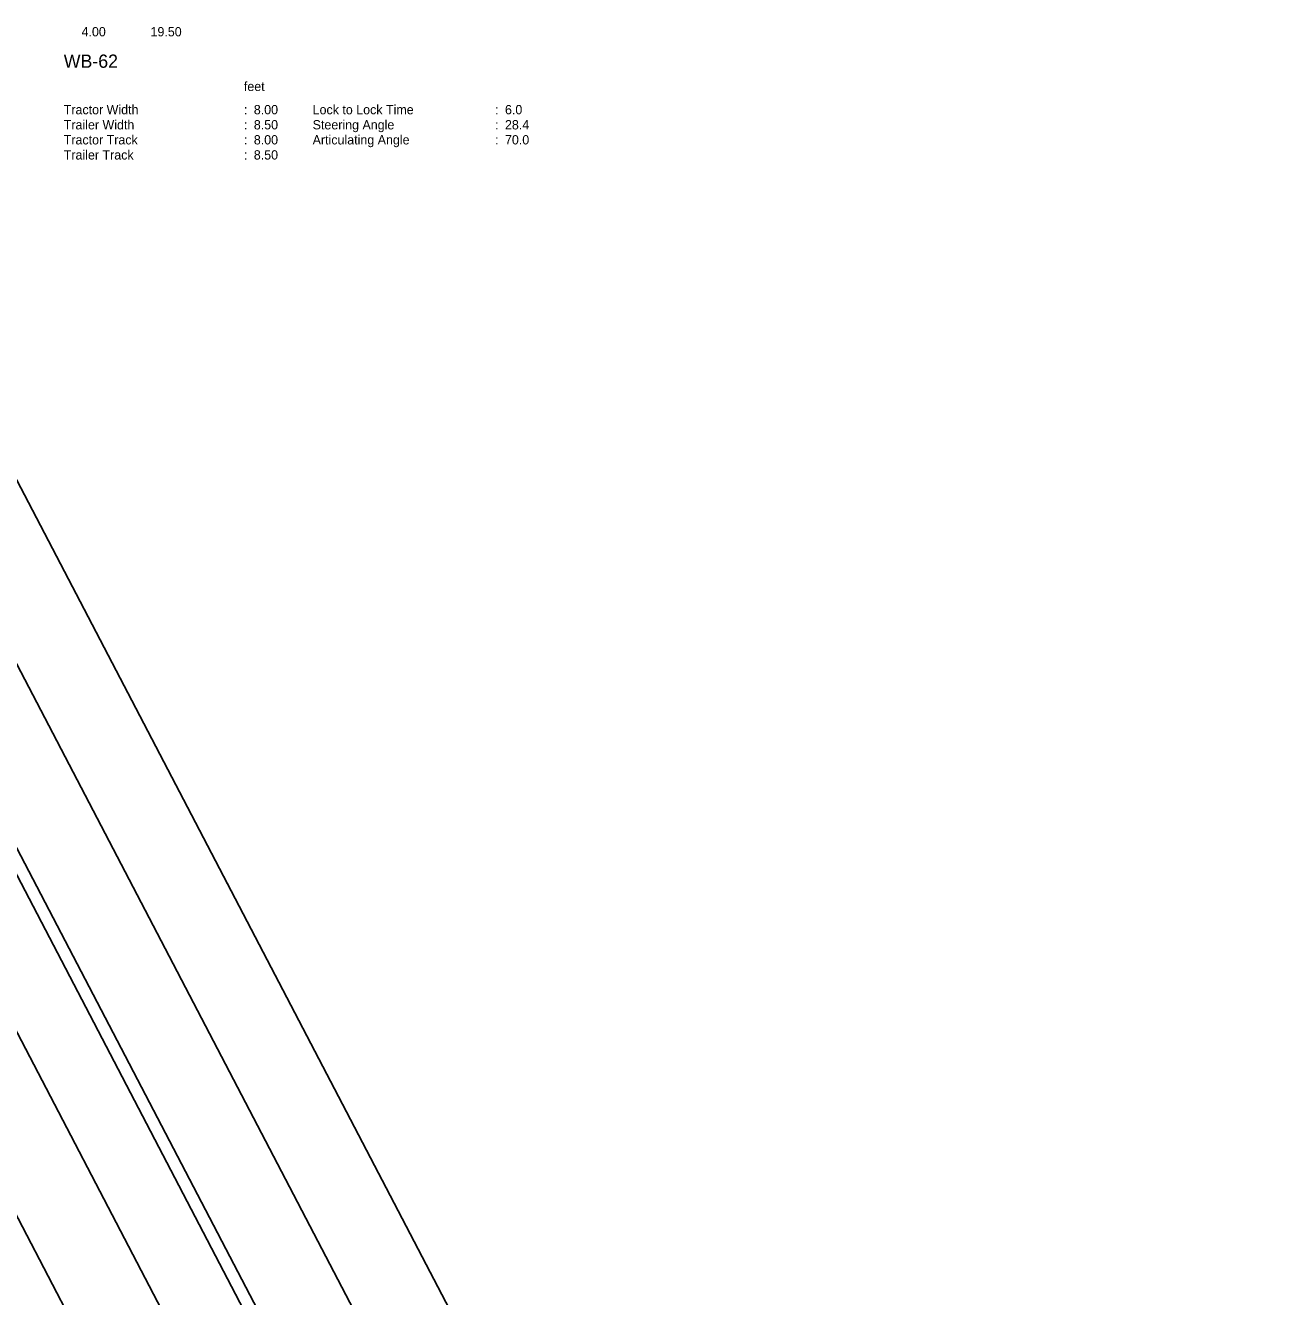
# Model space of a CAD drawing. Extents: x 2297881 to 2300600, y 559917 to 564426.
# Drawn here: x 2299069.8 to 2299244.6, y 562416.5 to 562595.7 of the extents above; entities that cross this region are included whole.
import ezdxf

# ---------------------------------------------------------------- set-up
doc = ezdxf.new("R2010")
doc.units = 0
for name, color, linetype in [('DR_X_Elev_Flow', 7, 'Continuous'), ('GE_X_Alignment', 7, 'Continuous'), ('PM_P_Lane_Line', 7, 'Continuous'), ('SV_X_Control_Cells_Found', 7, 'Continuous'), ('UT_X_Telecom_Cells', 7, 'Continuous'), ('VG_X_Cells', 7, 'Continuous')]:
    doc.layers.add(name, color=color, linetype=linetype)

msp = doc.modelspace()

# ---------------------------------------------------------------- linework, layer by layer
at = {"layer": 'GE_X_Alignment'}
msp.add_line((2298386.28, 563783.36), (2299396.64, 561847.4), dxfattribs=at)
at = {"layer": 'PM_P_Lane_Line'}
for p, q in [((2298467.65, 563579.35), (2299376.95, 561837.04)), ((2298843.32, 562963.26), (2299419.43, 561859.39))]:
    msp.add_line(p, q, dxfattribs=at)
at = {"layer": 'SV_X_Control_Cells_Found'}
msp.add_line((2299001.11, 562583.13), (2299365.23, 561885.43), dxfattribs=at)
at = {"layer": 'UT_X_Telecom_Cells'}
msp.add_line((2299022.38, 562594.23), (2299226.89, 562202.39), dxfattribs=at)
at = {"layer": 'VG_X_Cells'}
msp.add_line((2299011.74, 562588.68), (2299216.25, 562196.84), dxfattribs=at)

# ---------------------------------------------------------------- texts
at = {"layer": 'DR_X_Elev_Flow'}
for s, height, p in [('4.00', 1.312, (2299077.75, 562594.19)), ('19.50', 1.312, (2299087.47, 562594.19)), ('WB-62', 1.87, (2299075.24, 562589.76)), ('feet', 1.312, (2299100.63, 562586.48)), ('Tractor Width', 1.3123, (2299075.24, 562583.2)), ('8.00', 1.312, (2299102.03, 562583.2)), ('Lock to Lock Time', 1.3123, (2299110.32, 562583.2)), ('6.0', 1.312, (2299137.43, 562583.2)), (':', 1.31, (2299100.63, 562583.2)), (':', 1.31, (2299136.04, 562583.2)), ('Trailer Width', 1.3123, (2299075.24, 562581.07)), (':', 1.31, (2299100.63, 562581.07)), ('8.50', 1.312, (2299102.03, 562581.07)), ('Steering Angle', 1.3123, (2299110.32, 562581.07)), (':', 1.31, (2299136.04, 562581.07)), ('28.4', 1.312, (2299137.43, 562581.07)), ('Tractor Track', 1.3123, (2299075.24, 562578.95)), (':', 1.31, (2299100.63, 562578.95)), ('8.00', 1.312, (2299102.03, 562578.95)), ('Articulating Angle', 1.3123, (2299110.32, 562578.95)), (':', 1.31, (2299136.04, 562578.95)), ('70.0', 1.312, (2299137.43, 562578.95)), ('Trailer Track', 1.3123, (2299075.24, 562576.82)), (':', 1.31, (2299100.63, 562576.82)), ('8.50', 1.312, (2299102.03, 562576.82))]:
    msp.add_text(s, height=height, dxfattribs=at).set_placement(p)

doc.saveas('drawing.dxf')
